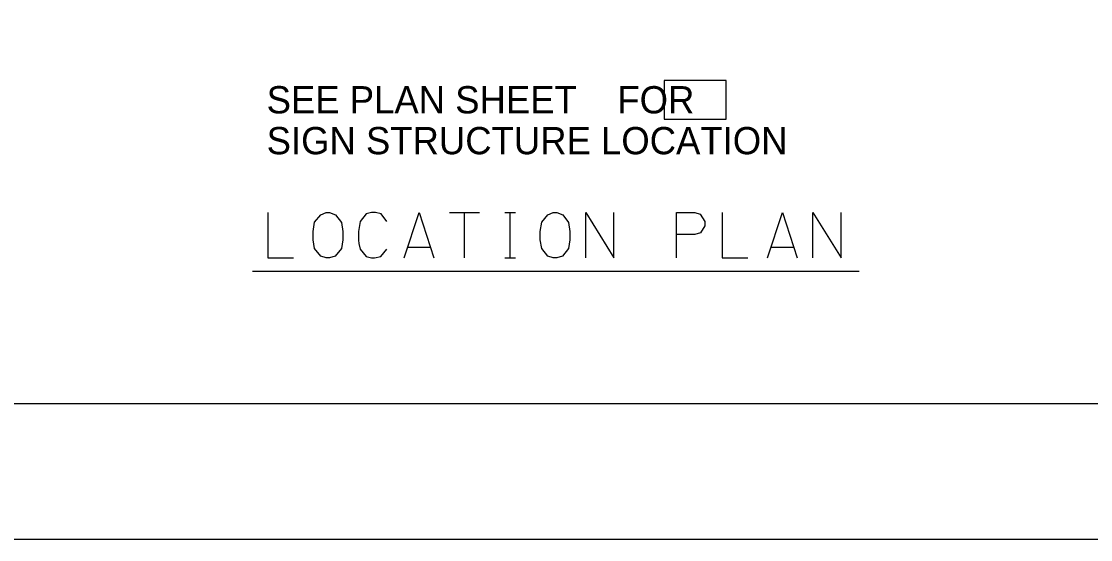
# Model space of a CAD drawing. Extents: x 3829340 to 3831660, y 499389 to 501171.
# Drawn here: x 3829843.8 to 3829961.7, y 499389.2 to 499446.4 of the extents above; entities that cross this region are included whole.
import ezdxf

# ---------------------------------------------------------------- set-up
doc = ezdxf.new("R2010")
doc.units = 0
for name, color, linetype in [('2', 7, 'Continuous'), ('DIM TXT', 7, 'Continuous'), ('PLT-BNDY', 7, 'Continuous')]:
    doc.layers.add(name, color=color, linetype=linetype)

msp = doc.modelspace()

# ---------------------------------------------------------------- linework, layer by layer
at = {"layer": '2'}
msp.add_line((3830165.96, 499404.19), (3829379.96, 499404.19), dxfattribs=at)
at = {"layer": 'DIM TXT'}
for p, q in [((3829890.99, 499425.29), (3829894.3, 499425.29)), ((3829892.64, 499420.28), (3829892.64, 499425.29)), ((3829892.64, 499420.28), (3829892.64, 499425.29)), ((3829897.1, 499425.29), (3829898.29, 499425.29)), ((3829897.69, 499420.28), (3829897.69, 499425.29)), ((3829886.37, 499421.47), (3829888.86, 499421.47)), ((3829926.45, 499421.47), (3829928.94, 499421.47)), ((3829897.1, 499420.28), (3829898.29, 499420.28)), ((3829869.28, 499418.8), (3829936.16, 499418.8))]:
    msp.add_line(p, q, dxfattribs=at)
msp.add_lwpolyline([(3829914.67, 499435.61), (3829921.49, 499435.61), (3829921.49, 499439.87), (3829914.67, 499439.87)], close=True, dxfattribs=at)
for points in [[(3829870.95, 499425.29), (3829870.95, 499420.28), (3829873.79, 499420.28)], [(3829877.38, 499425.29), (3829877.77, 499425.29), (3829878.44, 499425.02), (3829879.08, 499424.19), (3829879.23, 499423.2), (3829879.23, 499422.29), (3829879.08, 499421.31), (3829878.4, 499420.48), (3829877.77, 499420.28), (3829877.38, 499420.28), (3829876.79, 499420.48), (3829876.12, 499421.31), (3829875.96, 499422.29), (3829875.96, 499423.2), (3829876.12, 499424.23), (3829876.79, 499425.05), (3829877.38, 499425.29)], [(3829884.09, 499424.31), (3829883.45, 499425.13), (3829882.82, 499425.29), (3829882.39, 499425.29), (3829881.8, 499425.13), (3829881.13, 499424.31), (3829880.97, 499423.2), (3829880.97, 499422.61), (3829880.97, 499422.22), (3829881.01, 499421.86), (3829881.13, 499421.23), (3829881.8, 499420.44), (3829882.39, 499420.28), (3829882.74, 499420.28), (3829883.41, 499420.44), (3829884.09, 499421.23)], [(3829885.98, 499420.28), (3829887.64, 499425.29), (3829889.25, 499420.28)], [(3829902.43, 499425.29), (3829902.82, 499425.29), (3829903.49, 499425.02), (3829904.12, 499424.19), (3829904.28, 499423.2), (3829904.28, 499422.29), (3829904.12, 499421.31), (3829903.45, 499420.48), (3829902.82, 499420.28), (3829902.43, 499420.28), (3829901.84, 499420.48), (3829901.17, 499421.31), (3829901.01, 499422.29), (3829901.01, 499423.2), (3829901.17, 499424.23), (3829901.84, 499425.05), (3829902.43, 499425.29)], [(3829906.02, 499420.28), (3829906.02, 499425.29), (3829909.13, 499420.28), (3829909.13, 499425.29)], [(3829916.04, 499420.28), (3829916.04, 499425.29), (3829918.05, 499425.29), (3829918.64, 499425.09), (3829919.15, 499424.31), (3829919.15, 499423.83), (3829918.68, 499423.04), (3829918.05, 499422.85), (3829916.04, 499422.85)], [(3829921.05, 499425.29), (3829921.05, 499420.28), (3829923.89, 499420.28)], [(3829926.06, 499420.28), (3829927.71, 499425.29), (3829929.33, 499420.28)], [(3829931.07, 499420.28), (3829931.07, 499425.29), (3829934.18, 499420.28), (3829934.18, 499425.29)]]:
    msp.add_lwpolyline(points, dxfattribs=at)
at = {"layer": 'PLT-BNDY'}
msp.add_lwpolyline([(3829339.96, 499983.19), (3830180.96, 499983.19), (3830180.96, 499389.19), (3829339.96, 499389.19)], close=True, dxfattribs=at)

# ---------------------------------------------------------------- texts
at = {"layer": 'DIM TXT'}
for s, p in [('SEE PLAN SHEET    FOR', (3829870.83, 499436.23)), ('SIGN STRUCTURE LOCATION', (3829870.83, 499431.72))]:
    msp.add_text(s, height=3.0083, dxfattribs=at).set_placement(p)

doc.saveas('drawing.dxf')
